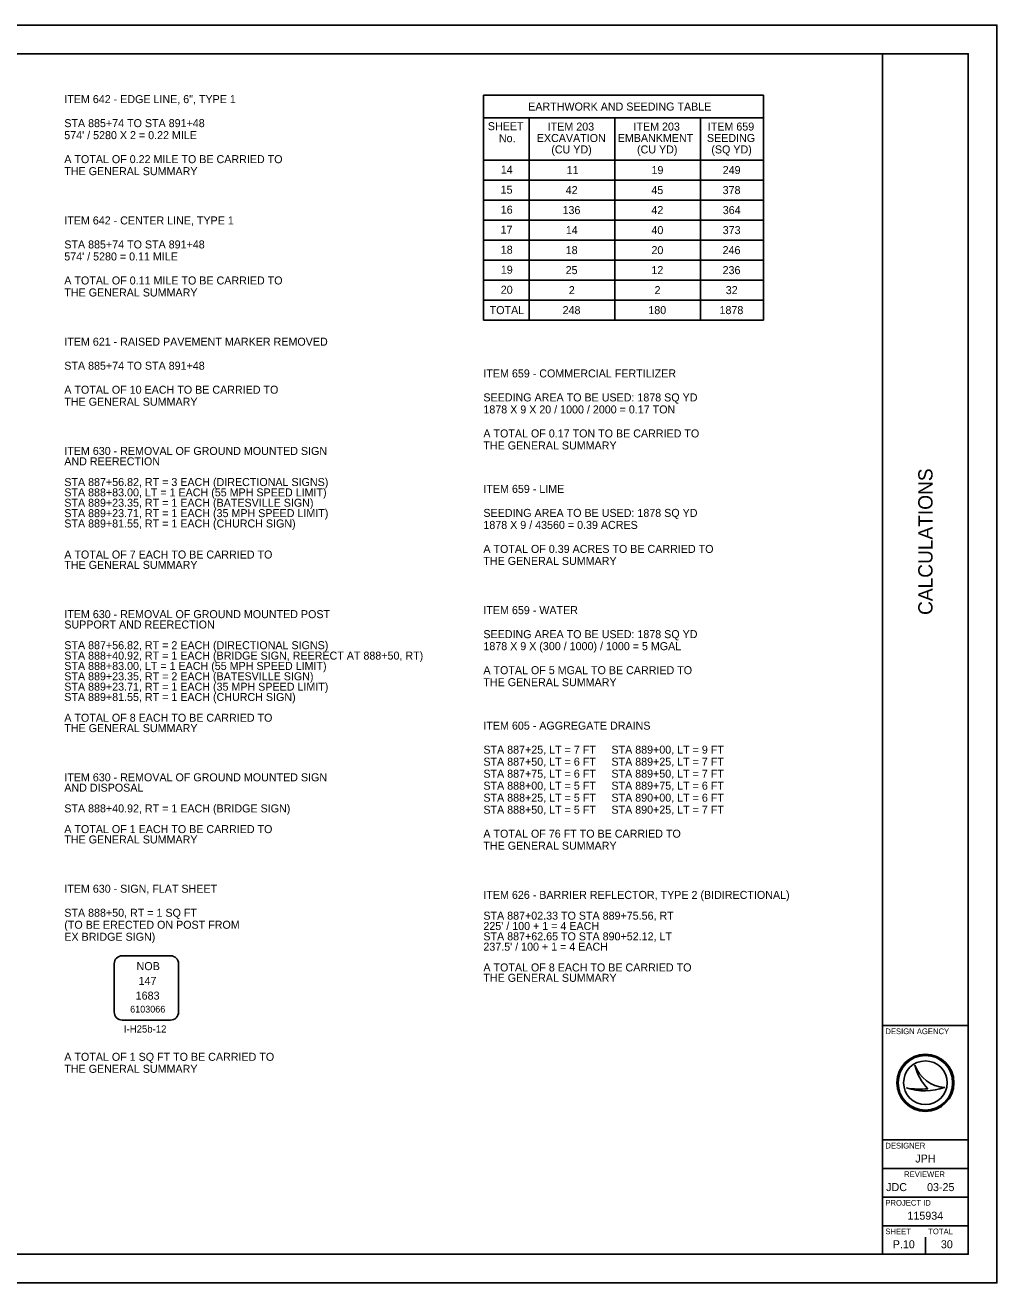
# Model space of a CAD drawing. Extents: x 0 to 34, y 0 to 22.
# Drawn here: x 17 to 34, y 0 to 22 of the extents above; entities that cross this region are included whole.
import ezdxf

# ---------------------------------------------------------------- set-up
doc = ezdxf.new("R2010")
doc.units = 0
for name, color, linetype in [('SH_Border', 7, 'Continuous'), ('SH_Cut_Line', 7, 'Continuous'), ('SH_Data', 7, 'Continuous'), ('SN_P_Signs', 7, 'Continuous'), ('SN_P_Text', 7, 'Continuous'), ('TX_P_1', 7, 'Continuous')]:
    doc.layers.add(name, color=color, linetype=linetype)

msp = doc.modelspace()

# ---------------------------------------------------------------- linework, layer by layer
at = {"layer": 'SH_Border'}
for p, q in [((32, 0.5), (32, 21.5)), ((32, 4.5), (33.5, 4.5)), ((32, 2.5), (33.5, 2.5)), ((32, 2), (33.5, 2)), ((32, 1.5), (33.5, 1.5)), ((32, 1), (33.5, 1))]:
    msp.add_line(p, q, dxfattribs=at)
msp.add_lwpolyline([(1.5, 21.5), (33.5, 21.5), (33.5, 0.5), (1.5, 0.5)], close=True, dxfattribs=at)
at = {"layer": 'SH_Cut_Line'}
msp.add_lwpolyline([(0, 0), (34, 0), (34, 22), (0, 22)], close=True, dxfattribs=at)
at = {"layer": 'SH_Data'}
for p, q in [((32.567, 3.81), (32.567, 3.81)), ((32.417, 3.41), (32.417, 3.41)), ((32.75, 3.5), (32.75, 3.5)), ((33.087, 3.419), (33.087, 3.419)), ((32.375, 0.675), (32.375, 0.675)), ((32.75, 0.5), (32.75, 0.8))]:
    msp.add_line(p, q, dxfattribs=at)
for radius in [0.5, 0.477, 0.477, 0.382]:
    msp.add_circle((32.75, 3.5), radius, dxfattribs=at)
for centre, radius, start, end in [((33.116, 3.998), 0.58, 198.9257, 198.9319), ((33.347, 3.97), 0.796, 191.6379, 191.6421), ((33.116, 3.998), 0.58, 198.9319, 267.1657), ((33.347, 3.97), 0.796, 191.6421, 226.0947), ((32.739, 4.37), 1.013, 251.4576, 290.0832), ((32.648, 4.654), 1.266, 259.4964, 259.4995), ((32.739, 4.37), 1.013, 251.4527, 251.4576), ((32.648, 4.654), 1.266, 259.4995, 276.6672)]:
    msp.add_arc(centre, radius, start, end, dxfattribs=at)
at = {"layer": 'SN_P_Signs'}
for points in [[(19.543, 5.722), (18.699, 5.722)], [(18.559, 5.581), (18.559, 4.737)], [(19.684, 4.737), (19.684, 5.581)], [(18.699, 4.597), (19.543, 4.597)]]:
    msp.add_lwpolyline(points, dxfattribs=at)
for centre, start, end in [((18.699, 5.581), 90, 180), ((19.543, 5.581), 0, 90), ((18.699, 4.737), 180, 270), ((19.543, 4.737), 270, 0)]:
    msp.add_arc(centre, 0.141, start, end, dxfattribs=at)
at = {"layer": 'TX_P_1'}
for p, q in [((29.917, 20.776), (25.017, 20.776)), ((25.017, 20.776), (25.017, 16.84)), ((29.917, 20.776), (29.917, 16.84)), ((29.917, 20.376), (25.017, 20.376)), ((25.817, 20.376), (25.817, 16.84)), ((27.317, 20.376), (27.317, 16.84)), ((28.817, 20.376), (28.817, 16.84)), ((29.917, 19.64), (25.017, 19.64)), ((29.917, 19.29), (25.017, 19.29)), ((29.917, 18.94), (25.017, 18.94)), ((29.917, 18.59), (25.017, 18.59)), ((29.917, 18.24), (25.017, 18.24)), ((29.917, 17.89), (25.017, 17.89)), ((29.917, 17.54), (25.017, 17.54)), ((29.917, 17.19), (25.017, 17.19)), ((29.917, 16.84), (25.017, 16.84))]:
    msp.add_line(p, q, dxfattribs=at)

# ---------------------------------------------------------------- texts
at = {"layer": 'SH_Data'}
msp.add_text('CALCULATIONS', height=0.25, rotation=90, dxfattribs=at).set_placement((32.875, 11.683))
for s, height, p in [('DESIGN AGENCY', 0.1, (32.05, 4.35)), ('DESIGNER', 0.1, (32.05, 2.35)), ('JPH', 0.14, (32.573, 2.105)), ('REVIEWER', 0.1, (32.378, 1.85)), ('JDC', 0.14, (32.064, 1.605)), ('03-25', 0.14, (32.779, 1.605)), ('PROJECT ID', 0.1, (32.05, 1.35)), ('115934', 0.14, (32.436, 1.105)), ('SHEET', 0.1, (32.05, 0.85)), ('TOTAL', 0.1, (32.8, 0.85)), ('P.10', 0.14, (32.179, 0.605)), ('30', 0.14, (33.021, 0.605))]:
    msp.add_text(s, height=height, dxfattribs=at).set_placement(p)
at = {"layer": 'SN_P_Signs'}
for s, height, p in [('NOB', 0.1407, (18.949, 5.47)), ('147', 0.1407, (18.984, 5.212)), ('1683', 0.1407, (18.933, 4.954)), ('6103066', 0.1181, (18.837, 4.728))]:
    msp.add_text(s, height=height, dxfattribs=at).set_placement(p)
at = {"layer": 'SN_P_Text'}
msp.add_text('I-H25b-12', height=0.125, dxfattribs=at).set_placement((18.728, 4.378))
at = {"layer": 'TX_P_1'}
for s, p in [('ITEM 642 - EDGE LINE, 6", TYPE 1', (17.685, 20.636)), ('EARTHWORK AND SEEDING TABLE', (25.801, 20.506)), ('STA 885+74 TO STA 891+48', (17.685, 20.216)), ('SHEET', (25.095, 20.163)), ('ITEM 203', (26.143, 20.156)), ('ITEM 203', (27.643, 20.156)), ('ITEM 659', (28.943, 20.156)), ("574' / 5280 X 2 = 0.22 MILE", (17.685, 20.006)), ('No.', (25.288, 19.953)), ('EXCAVATION', (25.951, 19.956)), ('EMBANKMENT', (27.367, 19.956)), ('SEEDING', (28.928, 19.956)), ('(CU YD)', (26.205, 19.756)), ('(CU YD)', (27.705, 19.756)), ('(SQ YD)', (29.005, 19.756)), ('A TOTAL OF 0.22 MILE TO BE CARRIED TO', (17.685, 19.586)), ('THE GENERAL SUMMARY', (17.685, 19.376)), ('14', (25.322, 19.402)), ('11', (26.473, 19.395)), ('19', (27.958, 19.395)), ('249', (29.204, 19.395)), ('15', (25.319, 19.052)), ('42', (26.457, 19.045)), ('45', (27.956, 19.045)), ('378', (29.203, 19.045)), ('16', (25.321, 18.702)), ('136', (26.402, 18.695)), ('42', (27.956, 18.695)), ('364', (29.205, 18.695)), ('ITEM 642 - CENTER LINE, TYPE 1', (17.685, 18.514)), ('17', (25.318, 18.352)), ('14', (26.459, 18.345)), ('40', (27.957, 18.345)), ('373', (29.204, 18.345)), ('STA 885+74 TO STA 891+48', (17.685, 18.094)), ('18', (25.321, 18.002)), ('18', (26.457, 17.995)), ('20', (27.957, 17.995)), ('246', (29.202, 17.995)), ("574' / 5280 = 0.11 MILE", (17.685, 17.884)), ('A TOTAL OF 0.11 MILE TO BE CARRIED TO', (17.685, 17.464)), ('19', (25.322, 17.652)), ('25', (26.456, 17.645)), ('12', (27.957, 17.645)), ('236', (29.202, 17.645)), ('THE GENERAL SUMMARY', (17.685, 17.254)), ('20', (25.321, 17.302)), ('2', (26.512, 17.295)), ('2', (28.012, 17.295)), ('32', (29.257, 17.295)), ('TOTAL', (25.127, 16.945)), ('248', (26.403, 16.945)), ('180', (27.903, 16.945)), ('1878', (29.148, 16.945)), ('ITEM 621 - RAISED PAVEMENT MARKER REMOVED', (17.685, 16.393)), ('STA 885+74 TO STA 891+48', (17.685, 15.973)), ('ITEM 659 - COMMERCIAL FERTILIZER', (25.017, 15.838)), ('A TOTAL OF 10 EACH TO BE CARRIED TO', (17.685, 15.553)), ('THE GENERAL SUMMARY', (17.685, 15.343)), ('SEEDING AREA TO BE USED: 1878 SQ YD', (25.017, 15.418)), ('1878 X 9 X 20 / 1000 / 2000 = 0.17 TON', (25.017, 15.208)), ('A TOTAL OF 0.17 TON TO BE CARRIED TO', (25.017, 14.788)), ('ITEM 630 - REMOVAL OF GROUND MOUNTED SIGN', (17.685, 14.482)), ('THE GENERAL SUMMARY', (25.017, 14.578)), ('AND REERECTION', (17.685, 14.3)), ('STA 887+56.82, RT = 3 EACH (DIRECTIONAL SIGNS)', (17.685, 13.938)), ('STA 888+83.00, LT = 1 EACH (55 MPH SPEED LIMIT)', (17.685, 13.757)), ('ITEM 659 - LIME', (25.017, 13.818)), ('STA 889+23.35, RT = 1 EACH (BATESVILLE SIGN)', (17.685, 13.576)), ('STA 889+23.71, RT = 1 EACH (35 MPH SPEED LIMIT)', (17.685, 13.394)), ('SEEDING AREA TO BE USED: 1878 SQ YD', (25.017, 13.398)), ('STA 889+81.55, RT = 1 EACH (CHURCH SIGN)', (17.685, 13.213)), ('1878 X 9 / 43560 = 0.39 ACRES', (25.017, 13.188)), ('A TOTAL OF 7 EACH TO BE CARRIED TO', (17.685, 12.67)), ('A TOTAL OF 0.39 ACRES TO BE CARRIED TO', (25.017, 12.768)), ('THE GENERAL SUMMARY', (17.685, 12.489)), ('THE GENERAL SUMMARY', (25.017, 12.558)), ('ITEM 630 - REMOVAL OF GROUND MOUNTED POST', (17.685, 11.627)), ('ITEM 659 - WATER', (25.017, 11.697)), ('SUPPORT AND REERECTION', (17.685, 11.446)), ('STA 887+56.82, RT = 2 EACH (DIRECTIONAL SIGNS)', (17.685, 11.084)), ('SEEDING AREA TO BE USED: 1878 SQ YD', (25.017, 11.277)), ('STA 888+40.92, RT = 1 EACH (BRIDGE SIGN, REERECT AT 888+50, RT)', (17.685, 10.902)), ('1878 X 9 X (300 / 1000) / 1000 = 5 MGAL', (25.017, 11.067)), ('STA 888+83.00, LT = 1 EACH (55 MPH SPEED LIMIT)', (17.685, 10.721)), ('A TOTAL OF 5 MGAL TO BE CARRIED TO', (25.017, 10.647)), ('STA 889+23.35, RT = 2 EACH (BATESVILLE SIGN)', (17.685, 10.54)), ('THE GENERAL SUMMARY', (25.017, 10.437)), ('STA 889+23.71, RT = 1 EACH (35 MPH SPEED LIMIT)', (17.685, 10.359)), ('STA 889+81.55, RT = 1 EACH (CHURCH SIGN)', (17.685, 10.178)), ('A TOTAL OF 8 EACH TO BE CARRIED TO', (17.685, 9.815)), ('THE GENERAL SUMMARY', (17.685, 9.634)), ('ITEM 605 - AGGREGATE DRAINS', (25.017, 9.677)), ('STA 887+25, LT = 7 FT', (25.017, 9.257)), ('STA 889+00, LT = 9 FT', (27.257, 9.257)), ('STA 887+50, LT = 6 FT', (25.017, 9.047)), ('STA 889+25, LT = 7 FT', (27.257, 9.047)), ('ITEM 630 - REMOVAL OF GROUND MOUNTED SIGN', (17.685, 8.773)), ('STA 887+75, LT = 6 FT', (25.017, 8.837)), ('STA 889+50, LT = 7 FT', (27.257, 8.837)), ('AND DISPOSAL', (17.685, 8.592)), ('STA 888+00, LT = 5 FT', (25.017, 8.627)), ('STA 889+75, LT = 6 FT', (27.257, 8.627)), ('STA 888+40.92, RT = 1 EACH (BRIDGE SIGN)', (17.685, 8.229)), ('STA 888+25, LT = 5 FT', (25.017, 8.417)), ('STA 890+00, LT = 6 FT', (27.257, 8.417)), ('STA 888+50, LT = 5 FT', (25.017, 8.207)), ('STA 890+25, LT = 7 FT', (27.257, 8.207)), ('A TOTAL OF 1 EACH TO BE CARRIED TO', (17.685, 7.867)), ('A TOTAL OF 76 FT TO BE CARRIED TO', (25.017, 7.787)), ('THE GENERAL SUMMARY', (17.685, 7.686)), ('THE GENERAL SUMMARY', (25.017, 7.577)), ('ITEM 630 - SIGN, FLAT SHEET', (17.685, 6.824)), ('ITEM 626 - BARRIER REFLECTOR, TYPE 2 (BIDIRECTIONAL)', (25.017, 6.716)), ('STA 888+50, RT = 1 SQ FT', (17.685, 6.404)), ('STA 887+02.33 TO STA 889+75.56, RT', (25.017, 6.353)), ('(TO BE ERECTED ON POST FROM ', (17.685, 6.194)), ("225' / 100 + 1 = 4 EACH", (25.017, 6.172)), ('EX BRIDGE SIGN)', (17.685, 5.984)), ('STA 887+62.65 TO STA 890+52.12, LT', (25.017, 5.991)), ("237.5' / 100 + 1 = 4 EACH", (25.017, 5.81)), ('A TOTAL OF 8 EACH TO BE CARRIED TO', (25.017, 5.447)), ('THE GENERAL SUMMARY', (25.017, 5.266)), ('A TOTAL OF 1 SQ FT TO BE CARRIED TO', (17.685, 3.884)), ('THE GENERAL SUMMARY', (17.685, 3.674))]:
    msp.add_text(s, height=0.14, dxfattribs=at).set_placement(p)

doc.saveas('drawing.dxf')
